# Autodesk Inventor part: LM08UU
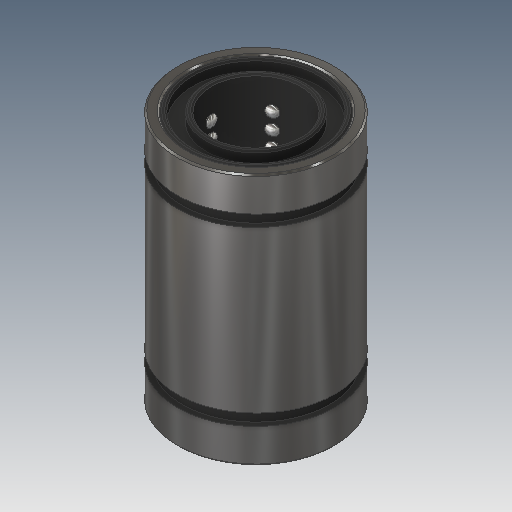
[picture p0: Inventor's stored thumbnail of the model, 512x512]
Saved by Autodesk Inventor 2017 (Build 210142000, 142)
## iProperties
Category: Diversos
Created: 2018-04
Part Number: LM08UU
Material: Generic
Document SubType Name: Modeling
Designer: Wesley Perez
Density: 1 g/cm^3
Appearance: Default
Description: Rolamento Linear 08mm
Author: Wesley Perez
Title: Rolamento Linear 08mm
Subject: Item Comercial
Keywords: Diversos
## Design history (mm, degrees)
node "Capa"
  feature "Superfície1"
node "Gaiola"
  feature "Superfície2"
node "Esferas"
  feature "Superfície3"
node "Sup2"
node "Sup3"
node "Sup4"
